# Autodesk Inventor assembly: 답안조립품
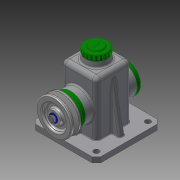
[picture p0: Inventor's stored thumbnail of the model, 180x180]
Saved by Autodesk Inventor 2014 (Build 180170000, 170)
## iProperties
Created: 2017-08
Part Number: 답안조립품
Document SubType Name: Assembly
Designer: user
Author: user
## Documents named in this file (14)
- E:\470825V1002\답안조립품.iam
- E:\470825V1002\본체.ipt
- E:\470825V1002\베어링 15 x 35 x 11.ipt
- E:\470825V1002\뒤커버.ipt
- E:\470825V1002\앞커버.ipt
- E:\470825V1002\축.ipt
- E:\470825V1002\멈춤링 15 x 1.ipt
- E:\470825V1002\볼트 M4 x 10.ipt
- E:\470825V1002\키 5 x 5 x 14.ipt
- E:\470825V1002\오일실 15 25 7.ipt
- E:\470825V1002\V-벨트풀리.ipt
- E:\470825V1002\와셔.ipt
- E:\470825V1002\볼트 M6 x 12.ipt
- E:\470825V1002\상부캡.ipt
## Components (1 placed, 1 different names)
1. V-벨트풀리:1 — 각도:1
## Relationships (1: Angle 1)
- 각도:1 [Angle]: V-벨트풀리:1
